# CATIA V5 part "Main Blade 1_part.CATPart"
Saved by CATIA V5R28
Part number: Main Blade 1_part
Definition: design
Nomenclature: Main Blade 1_part
Source: Unknown
Bounding box of the stored display mesh (mm): x -3.274 to 4.797, y -9.59 to 0.174, z 1.529 to 7.748
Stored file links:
  D:\paraturbo-cad\STEP\Turbocompressor_for_Christophe\Main Blade 1_part.CATPart
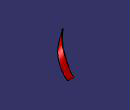
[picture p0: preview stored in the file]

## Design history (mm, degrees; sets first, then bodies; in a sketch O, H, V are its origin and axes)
Body1 "MANIFOLD_SOLID_BREP #30920" (main body)
  Solid1: solid without history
